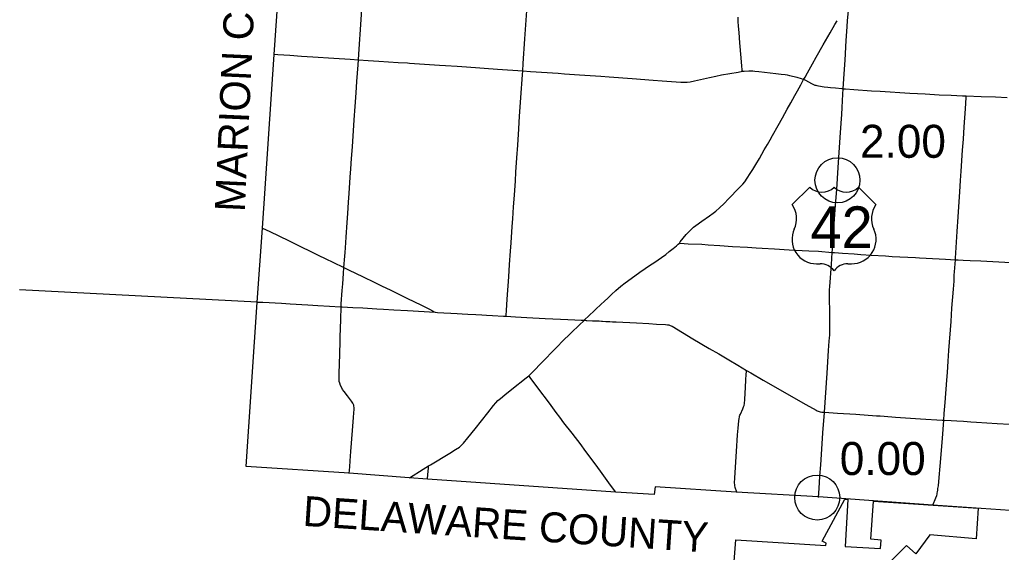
# Model space of a CAD drawing. Extents: x 9078 to 9739, y 4248 to 4966.
# Drawn here: x 9077.7 to 9241.2, y 4392.8 to 4481.6 of the extents above; entities that cross this region are included whole.
import ezdxf

# ---------------------------------------------------------------- set-up
doc = ezdxf.new("R2010")
doc.units = 0
for name, color, linetype in [('Default', 7, 'Continuous'), ('GM_X_Adjacent_County', 7, 'Continuous'), ('GM_X_Adjacent_County_Text', 7, 'Continuous'), ('GM_X_Corporation', 7, 'Continuous'), ('GM_X_County', 7, 'Continuous'), ('GM_X_County_Road', 7, 'Continuous'), ('GM_X_State_Route', 7, 'Continuous'), ('GM_X_Township_Road', 7, 'Continuous'), ('GM_X_US_Route', 7, 'Continuous'), ('GM_X_US_Shield', 7, 'Continuous')]:
    doc.layers.add(name, color=color, linetype=linetype)

msp = doc.modelspace()

# ---------------------------------------------------------------- linework, layer by layer
at = {"layer": 'Default'}
for centre in [(9213.93, 4454.85), (9210.56, 4401.97)]:
    msp.add_circle(centre, 3.75, dxfattribs=at)
at = {"layer": 'GM_X_Adjacent_County'}
msp.add_line((9117.29, 4434.55), (9077.7, 4436.59), dxfattribs=at)
at = {"layer": 'GM_X_Corporation'}
msp.add_lwpolyline([(9196.06, 4382.61), (9196.97, 4394.9), (9212.01, 4393.98), (9212.03, 4394.37), (9211.38, 4394.72), (9215.13, 4401.67), (9215.68, 4401.63), (9215.19, 4393.79), (9221.11, 4393.5), (9221.19, 4394.88), (9219.47, 4395.03), (9219.91, 4401.34), (9237.39, 4400.17), (9237.03, 4395.07), (9229.33, 4395.74), (9226.97, 4392.56), (9225.4, 4393.98), (9222.66, 4391.19)], dxfattribs=at)
at = {"layer": 'GM_X_County'}
msp.add_lwpolyline([(9250.73, 4399.27), (9229.79, 4400.68), (9210.75, 4402.08), (9197.05, 4402.87), (9183.54, 4403.77), (9183.41, 4402.48), (9176.98, 4402.87), (9145.62, 4405.03), (9142.56, 4405.26), (9132.59, 4406.02), (9115.41, 4407.15), (9117.29, 4434.55), (9118.13, 4446.85), (9120.12, 4475.84), (9122.16, 4505.46)], dxfattribs=at)
at = {"layer": 'GM_X_County_Road'}
for points in [[(9134.13, 4474.93), (9134.14, 4475.01), (9134.26, 4476.72), (9134.53, 4480.82), (9134.76, 4484.17), (9134.95, 4486.87), (9135.17, 4490.31), (9135.28, 4491.95), (9135.41, 4493.92), (9135.45, 4494.57), (9135.55, 4496.29), (9135.67, 4498.42), (9135.82, 4500.71), (9136, 4503.58), (9136.04, 4504.61)], [(9208.29, 4471.64), (9208.52, 4472.02), (9208.95, 4472.79), (9209.79, 4474.28), (9210.4, 4475.35), (9211.56, 4477.42), (9212.7, 4479.41), (9213.51, 4480.83), (9213.86, 4481.43)], [(9120.14, 4475.87), (9120.72, 4475.83), (9122.68, 4475.69), (9124.65, 4475.54), (9126.52, 4475.42), (9130.05, 4475.22), (9132.75, 4475.02), (9134.13, 4474.93)], [(9131.72, 4440.31), (9131.85, 4442.19), (9131.9, 4442.84), (9131.96, 4443.58), (9132.1, 4445.38), (9132.27, 4447.83), (9132.37, 4449.31), (9132.5, 4451.19), (9132.6, 4452.66), (9132.77, 4455.36), (9132.86, 4456.75), (9132.98, 4458.47), (9133.12, 4460.44), (9133.44, 4464.94), (9133.59, 4467.15), (9133.76, 4469.44), (9133.89, 4471.32), (9134.09, 4474.1), (9134.13, 4474.93)], [(9134.13, 4474.93), (9135.78, 4474.82), (9137.53, 4474.71)], [(9137.53, 4474.71), (9140.77, 4474.5), (9142.28, 4474.41)], [(9142.28, 4474.41), (9142.66, 4474.38), (9144.3, 4474.28), (9147.65, 4474.05), (9148.63, 4473.99), (9150.6, 4473.86), (9152.15, 4473.75), (9157.31, 4473.39), (9161.51, 4473.09)], [(9161.51, 4473.09), (9162.79, 4473.01), (9167.38, 4472.69), (9168.44, 4472.61), (9170.98, 4472.44), (9174.5, 4472.19), (9175.89, 4472.09), (9179.73, 4471.81), (9183.25, 4471.56), (9184.72, 4471.45), (9187.83, 4471.23), (9188.49, 4471.21), (9188.9, 4471.23), (9189.39, 4471.29), (9190.12, 4471.42), (9192.6, 4472), (9193.64, 4472.23), (9194.61, 4472.41), (9195.98, 4472.64), (9197.36, 4472.88), (9198.13, 4473.02), (9198.15, 4473.03)], [(9187.59, 4444.38), (9187.75, 4444.58), (9188.72, 4445.79), (9189, 4446.1), (9189.52, 4446.62), (9189.94, 4447.01), (9190.33, 4447.32), (9191.32, 4448.04), (9192.61, 4448.92), (9193.21, 4449.35), (9193.66, 4449.7), (9194.27, 4450.24), (9195.05, 4450.97), (9195.79, 4451.74), (9197.54, 4453.58), (9198.15, 4454.23), (9198.47, 4454.62), (9198.89, 4455.22), (9199.39, 4455.97), (9199.83, 4456.66), (9200.33, 4457.51), (9200.92, 4458.5), (9201.74, 4459.91), (9202.28, 4460.84), (9202.73, 4461.61), (9203.13, 4462.33), (9204.05, 4463.98), (9204.77, 4465.26), (9205.56, 4466.7), (9206.16, 4467.78), (9206.83, 4468.99), (9207.27, 4469.78), (9207.83, 4470.79), (9208.18, 4471.43), (9208.29, 4471.64)], [(9214.9, 4470.11), (9215.26, 4470.09), (9216.64, 4469.99), (9219.59, 4469.78), (9221.06, 4469.69), (9225.97, 4469.38), (9228.51, 4469.24), (9230.89, 4469.12), (9232.85, 4469.04), (9234.74, 4468.95), (9235.39, 4468.93)], [(9235.39, 4468.93), (9237.85, 4468.84), (9240.23, 4468.74), (9242.2, 4468.66)], [(9173.68, 4433.36), (9174.52, 4434.14), (9175.12, 4434.7), (9175.65, 4435.21), (9176.3, 4435.83), (9177.03, 4436.49), (9177.84, 4437.19), (9178.55, 4437.75), (9179.54, 4438.48), (9181.01, 4439.53), (9181.88, 4440.14), (9182.64, 4440.63), (9183.53, 4441.21), (9184.08, 4441.57), (9184.61, 4441.96), (9185.33, 4442.5), (9185.91, 4442.96), (9186.54, 4443.47), (9187.1, 4443.91), (9187.41, 4444.2), (9187.59, 4444.38)], [(9187.59, 4444.38), (9187.72, 4444.37), (9189.03, 4444.27), (9191.31, 4444.18), (9192.37, 4444.11), (9194.33, 4443.97), (9196.46, 4443.84), (9198.92, 4443.69), (9200.39, 4443.6), (9201.37, 4443.54), (9203.42, 4443.42), (9205.87, 4443.27), (9206.94, 4443.2), (9209.15, 4443.1), (9210.79, 4443.01), (9213.06, 4442.84)], [(9213.06, 4442.84), (9213.41, 4442.81), (9214.79, 4442.71), (9216.71, 4442.58), (9217.83, 4442.5), (9219.53, 4442.39), (9221.91, 4442.24), (9223.06, 4442.17), (9226.91, 4441.96), (9227.57, 4441.9), (9228.71, 4441.85), (9231.91, 4441.68), (9233.57, 4441.6)], [(9233.57, 4441.6), (9234.04, 4441.58), (9234.85, 4441.54), (9236.01, 4441.49), (9237.8, 4441.4), (9241.82, 4441.23), (9244.93, 4441.1), (9248.3, 4440.94), (9249.77, 4440.86), (9251.91, 4440.77), (9254.03, 4440.63), (9256.15, 4440.48), (9259.66, 4440.21), (9261.72, 4440.07), (9266.05, 4439.75), (9267.18, 4439.64), (9268.43, 4439.56), (9269.59, 4439.46)], [(9131.25, 4433.77), (9131.28, 4434.25), (9131.45, 4436.46), (9131.52, 4437.61), (9131.65, 4439.32), (9131.72, 4440.31)], [(9132.59, 4405.97), (9132.68, 4407.11), (9132.75, 4408.09), (9132.87, 4409.65), (9133.14, 4413.16), (9133.31, 4415.29), (9133.38, 4416.1), (9133.43, 4416.67), (9133.42, 4417), (9133.39, 4417.2), (9133.34, 4417.37), (9133.29, 4417.47), (9133.18, 4417.69), (9132.95, 4418.06), (9132.3, 4418.94), (9131.74, 4419.65), (9131.5, 4419.99), (9131.34, 4420.27), (9131.17, 4420.64), (9131.03, 4421.02), (9130.95, 4421.33), (9130.92, 4421.57), (9130.91, 4421.9), (9130.95, 4422.96), (9130.99, 4423.94), (9131, 4424.1), (9131, 4424.27), (9131, 4424.51), (9131.03, 4425.58), (9131.06, 4426.56), (9131.07, 4427.38), (9131.11, 4428.68), (9131.19, 4431.63), (9131.25, 4433.77)], [(9131.25, 4433.77), (9131.41, 4433.77), (9133.21, 4433.66), (9134.85, 4433.57), (9137.22, 4433.45), (9138.29, 4433.39), (9140.01, 4433.28), (9142.3, 4433.15), (9146.92, 4432.85)], [(9171.76, 4431.52), (9172.56, 4432.29), (9173.39, 4433.08), (9173.68, 4433.36)], [(9146.92, 4432.85), (9147.33, 4432.81), (9148.38, 4432.76), (9149.52, 4432.69), (9150.58, 4432.63), (9151.39, 4432.59), (9152.38, 4432.54), (9153.68, 4432.46), (9154.66, 4432.42), (9155.49, 4432.36), (9156.48, 4432.3), (9158.28, 4432.21), (9158.72, 4432.18)], [(9158.72, 4432.18), (9160.31, 4432.1), (9162.2, 4431.98), (9165.23, 4431.82), (9167.81, 4431.7), (9168.99, 4431.64), (9170.16, 4431.58), (9171.21, 4431.53), (9171.76, 4431.52)], [(9162.51, 4422.28), (9162.88, 4422.63), (9163.39, 4423.15), (9164.53, 4424.33), (9165.39, 4425.21), (9166.25, 4426.08), (9166.99, 4426.85), (9168.43, 4428.31), (9169.18, 4429.06), (9169.96, 4429.8), (9170.55, 4430.37), (9170.96, 4430.76), (9171.68, 4431.44), (9171.76, 4431.52)], [(9171.76, 4431.52), (9171.92, 4431.51), (9172.04, 4431.49), (9172.19, 4431.48), (9173.14, 4431.45), (9173.8, 4431.42), (9174.25, 4431.4), (9174.61, 4431.38)], [(9174.61, 4431.38), (9174.8, 4431.36), (9175.33, 4431.34), (9176.03, 4431.31), (9176.44, 4431.28), (9177.09, 4431.24), (9180.44, 4431.07), (9182.49, 4430.96), (9183.8, 4430.89), (9185.27, 4430.81), (9185.6, 4430.78), (9185.85, 4430.73), (9186.08, 4430.65), (9186.38, 4430.51), (9189.84, 4428.45), (9192.58, 4426.83), (9194.15, 4425.9), (9195.84, 4424.92), (9197.33, 4424.04), (9198.77, 4423.17)], [(9145.82, 4407.24), (9146.12, 4407.42), (9149.34, 4409.38), (9150.32, 4409.98), (9150.94, 4410.38), (9151.13, 4410.53), (9151.37, 4410.74), (9151.65, 4411.05), (9152.38, 4411.93), (9153.55, 4413.41), (9154.62, 4414.76), (9155.69, 4416.11), (9156.65, 4417.33), (9157.03, 4417.77), (9157.38, 4418.12), (9157.8, 4418.5), (9158.5, 4419.08), (9159.71, 4420.04), (9162.09, 4421.93), (9162.51, 4422.28)], [(9197.14, 4402.87), (9196.9, 4403.66), (9196.82, 4403.98), (9196.81, 4404.14), (9196.8, 4404.38), (9196.85, 4405.28), (9197.11, 4409.62), (9197.28, 4412.4), (9197.38, 4413.54), (9197.51, 4414.76), (9197.56, 4415.17), (9197.59, 4415.35), (9197.63, 4415.55), (9197.69, 4415.72), (9197.76, 4415.86), (9198.18, 4416.76), (9198.3, 4417.07), (9198.37, 4417.31), (9198.42, 4417.64), (9198.47, 4418.29), (9198.61, 4420.34), (9198.68, 4421.56), (9198.73, 4422.53), (9198.75, 4422.92), (9198.77, 4423.17)], [(9198.77, 4423.17), (9199.5, 4422.73), (9201.57, 4421.54), (9208.67, 4417.48), (9210.37, 4416.52), (9210.56, 4416.41), (9210.74, 4416.34), (9210.88, 4416.29), (9211.03, 4416.26), (9211.32, 4416.22), (9211.52, 4416.2), (9211.74, 4416.18)], [(9142.63, 4405.28), (9144.93, 4406.69), (9145.82, 4407.24)]]:
    msp.add_lwpolyline(points, dxfattribs=at)
at = {"layer": 'GM_X_State_Route'}
for points in [[(9198.1, 4473.08), (9198.08, 4473.1), (9198.06, 4473.15), (9198.04, 4473.21), (9198.03, 4473.3), (9198, 4473.87), (9197.89, 4475.26), (9197.68, 4477.79), (9197.55, 4479.51), (9197.46, 4480.57), (9197.4, 4481.31), (9197.37, 4482.05)], [(9214.9, 4470.11), (9214.67, 4470.12), (9213.61, 4470.2), (9212.79, 4470.26), (9212.3, 4470.31), (9211.73, 4470.39), (9210.76, 4470.54), (9210.52, 4470.59), (9210.36, 4470.63), (9210.2, 4470.68), (9209.97, 4470.78), (9209.68, 4470.93), (9209.17, 4471.2), (9208.67, 4471.47), (9208.45, 4471.58), (9208.29, 4471.64), (9208.22, 4471.67), (9207.91, 4471.77), (9207.2, 4471.97), (9206.41, 4472.18), (9206.01, 4472.28), (9205.61, 4472.35), (9205.21, 4472.41), (9204.56, 4472.49), (9203.66, 4472.58), (9201.79, 4472.8), (9200.81, 4472.93), (9200.16, 4473.01), (9199.83, 4473.03), (9199.51, 4473.04), (9199.18, 4473.04), (9198.36, 4472.99), (9198.3, 4472.99), (9198.24, 4472.99), (9198.19, 4473.01), (9198.15, 4473.03), (9198.12, 4473.06), (9198.1, 4473.08)]]:
    msp.add_lwpolyline(points, dxfattribs=at)
at = {"layer": 'GM_X_Township_Road'}
for points in [[(9161.51, 4473.09), (9161.58, 4474.32), (9161.85, 4478.41), (9162.16, 4483.08), (9162.33, 4485.62), (9162.42, 4487.26), (9162.56, 4489.31), (9162.63, 4490.29), (9162.76, 4492.09), (9162.82, 4493.15), (9163, 4495.77), (9163.09, 4497.17), (9163.28, 4500.03), (9163.46, 4502.65), (9163.47, 4502.78)], [(9158.72, 4432.18), (9158.74, 4432.39), (9158.79, 4433.13), (9158.92, 4435.02), (9159.17, 4438.78), (9159.31, 4440.83), (9159.46, 4443.04), (9159.55, 4444.43), (9159.74, 4447.13), (9159.84, 4448.44), (9159.98, 4450.41), (9160.12, 4452.37), (9160.27, 4454.75), (9160.37, 4456.22), (9160.53, 4458.6), (9160.67, 4460.73), (9160.84, 4463.43), (9160.98, 4465.56), (9161.08, 4467.03), (9161.2, 4468.67), (9161.46, 4472.44), (9161.51, 4473.09)], [(9233.57, 4441.6), (9233.6, 4441.88), (9233.87, 4446.3), (9234.04, 4448.76), (9234.32, 4452.93), (9234.44, 4454.82), (9234.54, 4456.37), (9234.78, 4459.89), (9234.91, 4461.69), (9235.05, 4463.74), (9235.25, 4466.76), (9235.37, 4468.65), (9235.38, 4468.73), (9235.39, 4468.93)], [(9118.15, 4446.89), (9119.37, 4446.31), (9122.46, 4444.8), (9124.6, 4443.75), (9126.08, 4443.05), (9126.67, 4442.77), (9127.55, 4442.34), (9128.57, 4441.82), (9129.98, 4441.14), (9131.61, 4440.37), (9131.72, 4440.31)], [(9231.64, 4414.87), (9231.72, 4415.95), (9231.86, 4417.83), (9232.15, 4421.51), (9232.25, 4422.82), (9232.38, 4424.7), (9232.5, 4426.5), (9232.84, 4431.33), (9233, 4433.54), (9233.24, 4436.73), (9233.34, 4438.04), (9233.37, 4438.61), (9233.37, 4439.02), (9233.41, 4439.59), (9233.57, 4441.6)], [(9131.72, 4440.31), (9132.49, 4439.93), (9134.92, 4438.75), (9136.76, 4437.85), (9138.09, 4437.21), (9139.42, 4436.57), (9142.21, 4435.19), (9144.65, 4434.01), (9145.97, 4433.37), (9146.49, 4433.1), (9146.74, 4432.95), (9146.92, 4432.85)], [(9117.31, 4434.55), (9118.18, 4434.52), (9121.29, 4434.35), (9122.77, 4434.27), (9125.72, 4434.1), (9127.35, 4434), (9129.32, 4433.89), (9131.12, 4433.78), (9131.25, 4433.77)], [(9176.98, 4402.92), (9175.84, 4404.44), (9174.73, 4405.98), (9173.71, 4407.37), (9171.87, 4409.88), (9171.23, 4410.73), (9169.73, 4412.68), (9168.37, 4414.43), (9167.67, 4415.34), (9167.09, 4416.13), (9166.8, 4416.53), (9166.52, 4416.91), (9165.94, 4417.7), (9164.03, 4420.26), (9162.75, 4421.97), (9162.6, 4422.17), (9162.51, 4422.28)], [(9211.74, 4416.18), (9213.95, 4416.04), (9216.97, 4415.84), (9220.41, 4415.61), (9221.02, 4415.57)], [(9221.02, 4415.57), (9221.72, 4415.52), (9223.6, 4415.37), (9227.78, 4415.1), (9231.38, 4414.89), (9231.64, 4414.87)], [(9229.79, 4400.68), (9230.33, 4401.93), (9230.46, 4402.32), (9230.51, 4402.52), (9230.56, 4402.72), (9230.6, 4402.92), (9230.64, 4403.2), (9230.67, 4403.45), (9230.73, 4403.93), (9230.88, 4405.32), (9231.06, 4407.2), (9231.37, 4411.12), (9231.48, 4412.59), (9231.59, 4414.07), (9231.64, 4414.87)], [(9231.64, 4414.87), (9232.85, 4414.81), (9233.83, 4414.74), (9234.9, 4414.68), (9236.12, 4414.6), (9237.11, 4414.53), (9240.54, 4414.32), (9244.64, 4414.07), (9247.25, 4413.9), (9250.94, 4413.66), (9251.85, 4413.61)], [(9145.65, 4405.08), (9145.72, 4405.81), (9145.8, 4406.85), (9145.81, 4407.09), (9145.82, 4407.24)]]:
    msp.add_lwpolyline(points, dxfattribs=at)
at = {"layer": 'GM_X_US_Route'}
for points in [[(9214.9, 4470.11), (9215.05, 4472.57), (9215.19, 4474.86), (9215.39, 4478.14), (9215.54, 4480.43), (9215.62, 4481.49), (9215.75, 4483.12)], [(9210.76, 4401.96), (9210.86, 4403.48), (9211, 4405.53), (9211.14, 4407.41), (9211.38, 4410.93), (9211.51, 4412.73), (9211.74, 4416.16), (9211.74, 4416.18), (9212.2, 4422.71), (9212.46, 4426.47), (9212.57, 4428.04), (9212.61, 4428.58), (9212.63, 4429.06), (9212.66, 4429.92), (9212.67, 4430.9), (9212.63, 4433.11), (9212.59, 4435), (9212.59, 4435.58), (9212.6, 4436.15), (9212.62, 4436.57), (9212.65, 4437.13), (9212.92, 4440.81), (9213.06, 4442.84), (9213.14, 4443.92), (9213.23, 4445.27), (9213.4, 4447.6), (9213.62, 4450.71), (9213.8, 4453.33), (9214.05, 4457.01), (9214.4, 4462.01), (9214.55, 4464.39), (9214.64, 4465.8), (9214.71, 4467), (9214.84, 4469.21), (9214.9, 4470.11)]]:
    msp.add_lwpolyline(points, dxfattribs=at)
at = {"layer": 'GM_X_US_Shield'}
for p, q in [((9209.3, 4453.69), (9206.4, 4450.79)), ((9220.32, 4450.79), (9217.42, 4453.69)), ((9210.46, 4440.93), (9211.04, 4440.93)), ((9215.68, 4440.93), (9216.26, 4440.93))]:
    msp.add_line(p, q, dxfattribs=at)
for centre, radius, start, end in [((9211.33, 4455.76), 2.9, 225.573, 314.427), ((9215.39, 4455.76), 2.9, 225.573, 314.427), ((9203.07, 4448.46), 4.06, 334.5471, 35.0009), ((9223.65, 4448.46), 4.06, 144.9991, 205.4529), ((9210.41, 4444.99), 4.06, 154.8319, 270.6383), ((9216.3, 4444.99), 4.06, 269.3617, 25.1681), ((9211.04, 4438.03), 2.9, 36.8699, 90), ((9215.68, 4438.03), 2.9, 90, 143.1301)]:
    msp.add_arc(centre, radius, start, end, dxfattribs=at)

# ---------------------------------------------------------------- texts
at = {"layer": 'Default'}
for s, p in [('2.00', (9217.68, 4458.6)), ('0.00', (9214.31, 4405.72))]:
    msp.add_text(s, height=5.5, dxfattribs=at).set_placement(p)
at = {"layer": 'GM_X_Adjacent_County_Text'}
for s, rotation, p in [('MARION COUNTY', 87.3751, (9115.2, 4449.51)), ('DELAWARE COUNTY', 356.2231, (9124.77, 4397.26))]:
    msp.add_text(s, height=5, rotation=rotation, dxfattribs=at).set_placement(p)
at = {"layer": 'GM_X_US_Shield'}
msp.add_text('42', height=6.961, dxfattribs=at).set_placement((9209.44, 4443.54))

doc.saveas('drawing.dxf')
